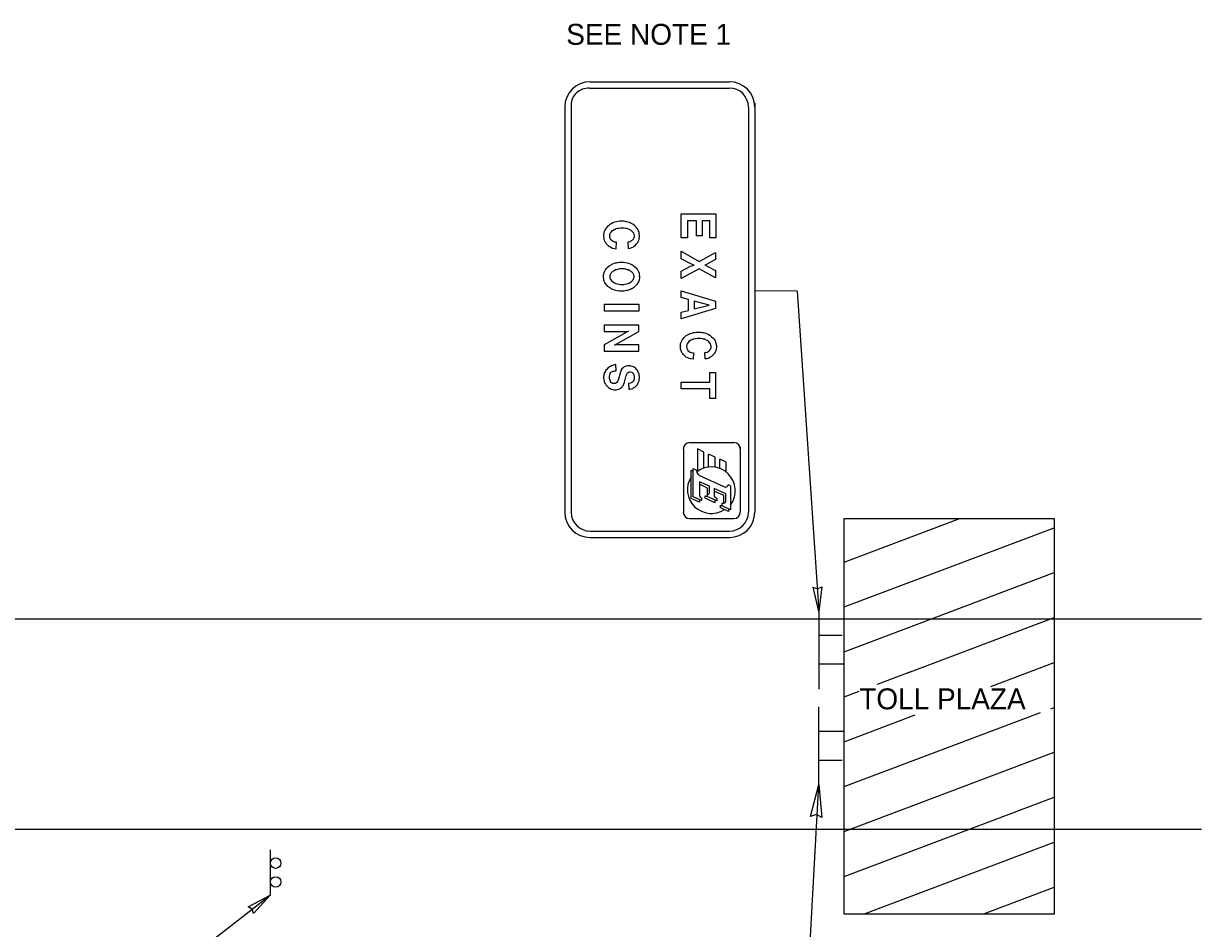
# Model space of a CAD drawing. Extents: x 46672 to 47298, y 5424 to 5829.
# Drawn here: x 46830.9 to 46988.5, y 5615.3 to 5736.4 of the extents above; entities that cross this region are included whole.
import ezdxf

# ---------------------------------------------------------------- set-up
doc = ezdxf.new("R2010")
doc.units = 0
for name, color, linetype in [('LeaderLine_dp', 7, 'Continuous'), ('RoadwayMisc', 7, 'Continuous'), ('SignSupport', 7, 'Continuous'), ('TextLabel', 7, 'Continuous'), ('TextShtNo', 7, 'Continuous')]:
    doc.layers.add(name, color=color, linetype=linetype)

msp = doc.modelspace()

# ---------------------------------------------------------------- linework, layer by layer
at = {"layer": 'LeaderLine_dp'}
for p, q in [((46934.39, 5700.63), (46928.71, 5700.64)), ((46934.39, 5700.63), (46937.26, 5657.75)), ((46934.39, 5582.49), (46937.26, 5634.61)), ((46845.12, 5605.25), (46863.86, 5619.8))]:
    msp.add_line(p, q, dxfattribs=at)
for points in [[(46937.26, 5657.75), (46936.52, 5660.99), (46937.1, 5660.78), (46937.67, 5661.05)], [(46937.26, 5634.61), (46937.68, 5630.2), (46936.95, 5630.57), (46936.15, 5630.32)], [(46863.86, 5619.8), (46861.62, 5617.34), (46861.46, 5617.93), (46860.92, 5618.25)]]:
    msp.add_lwpolyline(points, close=True, dxfattribs=at)
at = {"layer": 'RoadwayMisc'}
for p, q in [((46940.64, 5617.26), (46940.64, 5670.2)), ((46940.64, 5670.2), (46968.77, 5670.2)), ((46940.64, 5664.37), (46956.01, 5670.16)), ((46968.77, 5670.2), (46968.77, 5617.26)), ((46940.64, 5658.36), (46968.77, 5668.96)), ((46940.64, 5652.35), (46968.77, 5662.95)), ((46718.46, 5656.76), (46988.46, 5656.76)), ((46949.18, 5649.55), (46968.77, 5656.94)), ((46960.28, 5647.73), (46968.77, 5650.93)), ((46945.12, 5648.02), (46949.72, 5649.76)), ((46940.64, 5646.33), (46942.66, 5647.09)), ((46940.64, 5634.31), (46966.95, 5644.23)), ((46940.64, 5640.32), (46950.14, 5643.91)), ((46968.3, 5644.74), (46968.77, 5644.92)), ((46940.64, 5628.3), (46968.77, 5638.91)), ((46940.64, 5622.29), (46968.77, 5632.89)), ((46718.46, 5628.64), (46988.46, 5628.64)), ((46943.26, 5617.26), (46968.77, 5626.88)), ((46959.2, 5617.26), (46968.77, 5620.87)), ((46968.77, 5617.26), (46940.64, 5617.26))]:
    msp.add_line(p, q, dxfattribs=at)
at = {"layer": 'SignSupport'}
for p, q in [((46937.26, 5657.75), (46937.26, 5647.36)), ((46940.38, 5654.53), (46937.26, 5654.53)), ((46940.6, 5650.68), (46937.26, 5650.68)), ((46937.26, 5634.61), (46937.26, 5645)), ((46940.6, 5641.68), (46937.26, 5641.68)), ((46940.38, 5637.83), (46937.26, 5637.83)), ((46863.86, 5625.84), (46863.86, 5619.8))]:
    msp.add_line(p, q, dxfattribs=at)
for centre in [(46864.59, 5624.08), (46864.59, 5621.56)]:
    msp.add_circle(centre, 0.703, dxfattribs=at)
at = {"layer": 'TextShtNo'}
for p, q in [((46906.58, 5727.79), (46925.31, 5727.79)), ((46906.67, 5728.64), (46925.31, 5728.64)), ((46928.7, 5725.75), (46928.7, 5671.04)), ((46903.29, 5725.25), (46903.29, 5671.04)), ((46904.13, 5725.57), (46904.13, 5671.04)), ((46927.85, 5725.25), (46927.85, 5671.04)), ((46913.29, 5702.55), (46913.29, 5702.59)), ((46919.98, 5680.36), (46925.91, 5680.36)), ((46919.14, 5679.51), (46919.14, 5671.04)), ((46921.03, 5679.5), (46921.03, 5676.49)), ((46921.9, 5679.09), (46921.03, 5679.5)), ((46921.9, 5676.94), (46921.9, 5679.09)), ((46922.52, 5677.07), (46922.52, 5678.81)), ((46923.39, 5678.41), (46922.52, 5678.81)), ((46926.76, 5679.75), (46926.76, 5671.04)), ((46923.39, 5677.06), (46923.39, 5678.41)), ((46924.01, 5676.9), (46924.01, 5678.12)), ((46924.88, 5677.72), (46924.01, 5678.12)), ((46924.88, 5676.41), (46924.88, 5677.72)), ((46920.2, 5672.87), (46920.2, 5676.65)), ((46920.2, 5676.65), (46920.46, 5676.52)), ((46920.46, 5676.88), (46920.92, 5676.67)), ((46920.46, 5673.11), (46920.46, 5676.88)), ((46920.92, 5676.67), (46920.92, 5676.51)), ((46921.29, 5675.97), (46924.63, 5674.43)), ((46922.64, 5674.5), (46921.29, 5675.12)), ((46921.29, 5675.12), (46921.29, 5673.39)), ((46922.38, 5674.26), (46921.29, 5674.77)), ((46922.38, 5673.43), (46922.38, 5674.26)), ((46922.64, 5673.63), (46922.64, 5674.5)), ((46924.83, 5673.49), (46923.27, 5674.21)), ((46923.27, 5674.21), (46923.27, 5673.31)), ((46924.56, 5673.25), (46923.27, 5673.85)), ((46925.45, 5674.58), (46925.14, 5674.72)), ((46925.45, 5674.58), (46925.45, 5671.37)), ((46921.31, 5672.36), (46920.2, 5672.87)), ((46921.57, 5672.59), (46920.46, 5673.11)), ((46921.31, 5672.72), (46921.31, 5672.36)), ((46921.57, 5672.97), (46921.57, 5672.59)), ((46922.04, 5672.91), (46922.04, 5673.22)), ((46923.34, 5672.31), (46922.04, 5672.91)), ((46922.31, 5673.46), (46922.31, 5673.14)), ((46923.6, 5672.54), (46922.31, 5673.14)), ((46923.34, 5672.66), (46923.34, 5672.31)), ((46923.6, 5672.92), (46923.49, 5672.97)), ((46923.6, 5672.92), (46923.6, 5672.54)), ((46924.34, 5671.88), (46924.34, 5672.26)), ((46924.56, 5672.23), (46924.56, 5673.25)), ((46924.83, 5672.53), (46924.83, 5673.49)), ((46924.08, 5671.96), (46924.08, 5671.65)), ((46925.19, 5671.13), (46924.08, 5671.65)), ((46925.45, 5671.37), (46924.34, 5671.88)), ((46925.19, 5671.49), (46925.19, 5671.13)), ((46919.98, 5670.19), (46925.91, 5670.19)), ((46906.67, 5668.5), (46925.31, 5668.5)), ((46906.67, 5667.65), (46925.31, 5667.65))]:
    msp.add_line(p, q, dxfattribs=at)
for points in [[(46918.85, 5710.97), (46923.47, 5710.97), (46923.47, 5707.73), (46922.7, 5707.73), (46922.7, 5710.01), (46921.68, 5710.01), (46921.68, 5708.03), (46920.92, 5708.03), (46920.92, 5710.01), (46919.68, 5710.01), (46919.68, 5707.73), (46918.85, 5707.73), (46918.85, 5710.97)], [(46911.76, 5706.32), (46912.01, 5706.36), (46912.27, 5706.46), (46912.45, 5706.56), (46912.56, 5706.62), (46912.74, 5706.79), (46912.85, 5706.89), (46912.96, 5707.02), (46913.03, 5707.13), (46913.1, 5707.26), (46913.18, 5707.43), (46913.21, 5707.52), (46913.25, 5707.66), (46913.29, 5707.92), (46913.29, 5708.06), (46913.25, 5708.33), (46913.21, 5708.46), (46913.1, 5708.76), (46913.03, 5708.89), (46912.92, 5709.06), (46912.81, 5709.19), (46912.6, 5709.39), (46912.38, 5709.56), (46912.16, 5709.69), (46911.94, 5709.79), (46911.72, 5709.86), (46911.54, 5709.89), (46911.4, 5709.93), (46911.21, 5709.96), (46910.96, 5709.96), (46910.63, 5709.96), (46910.38, 5709.93), (46910.2, 5709.89), (46909.94, 5709.83), (46909.72, 5709.76), (46909.58, 5709.69), (46909.4, 5709.59), (46909.25, 5709.49), (46909.11, 5709.36), (46908.96, 5709.23), (46908.81, 5709.06), (46908.74, 5708.96), (46908.71, 5708.89), (46908.63, 5708.76), (46908.56, 5708.62), (46908.52, 5708.49), (46908.49, 5708.39), (46908.45, 5708.13), (46908.45, 5707.96), (46908.49, 5707.69), (46908.52, 5707.56), (46908.56, 5707.43), (46908.6, 5707.33), (46908.67, 5707.19), (46908.71, 5707.13), (46908.78, 5707.02), (46908.89, 5706.89), (46908.96, 5706.82), (46909.03, 5706.76), (46909.11, 5706.69), (46909.25, 5706.59), (46909.43, 5706.49), (46909.65, 5706.39), (46909.87, 5706.32), (46910.16, 5706.29)], [(46910.2, 5707.16), (46909.91, 5707.19), (46909.76, 5707.26), (46909.61, 5707.36), (46909.47, 5707.49), (46909.4, 5707.62), (46909.32, 5707.79), (46909.29, 5707.96), (46909.29, 5708.06), (46909.32, 5708.26), (46909.36, 5708.36), (46909.47, 5708.53), (46909.65, 5708.73), (46909.87, 5708.86), (46910.01, 5708.93), (46910.16, 5708.99), (46910.31, 5709.03), (46910.49, 5709.06), (46910.71, 5709.09), (46910.81, 5709.09), (46911, 5709.09), (46911.03, 5709.09), (46911.21, 5709.09), (46911.43, 5709.06), (46911.54, 5709.03), (46911.69, 5708.99), (46911.83, 5708.93), (46912.05, 5708.83), (46912.2, 5708.73), (46912.27, 5708.66), (46912.45, 5708.43), (46912.52, 5708.26), (46912.56, 5707.99), (46912.56, 5707.89), (46912.52, 5707.76), (46912.49, 5707.66), (46912.41, 5707.56), (46912.38, 5707.49), (46912.3, 5707.43), (46912.2, 5707.33), (46912.05, 5707.26), (46911.98, 5707.22), (46911.72, 5707.19)], [(46910.16, 5706.29), (46910.2, 5707.16)], [(46911.72, 5707.19), (46911.76, 5706.32)], [(46918.85, 5705.95), (46921.28, 5704.6), (46923.46, 5705.79), (46923.46, 5704.83), (46922.26, 5704.2), (46922.01, 5704.11), (46922.26, 5704.01), (46923.46, 5703.38), (46923.46, 5702.39), (46921.28, 5703.61), (46918.85, 5702.29), (46918.85, 5703.28), (46920.12, 5703.94), (46920.59, 5704.11), (46920.16, 5704.27), (46918.85, 5704.96), (46918.85, 5705.95)], [(46910.85, 5700.62), (46910.6, 5700.62), (46910.27, 5700.65), (46910.12, 5700.69), (46909.94, 5700.75), (46909.72, 5700.82), (46909.58, 5700.89), (46909.47, 5700.95), (46909.29, 5701.05), (46909.18, 5701.15), (46909.03, 5701.25), (46908.89, 5701.42), (46908.81, 5701.52), (46908.74, 5701.62), (46908.63, 5701.79), (46908.56, 5701.95), (46908.52, 5702.05), (46908.49, 5702.25), (46908.45, 5702.45), (46908.45, 5702.52), (46908.45, 5702.69), (46908.49, 5702.92), (46908.52, 5703.02), (46908.56, 5703.16), (46908.6, 5703.22), (46908.63, 5703.32), (46908.67, 5703.39), (46908.74, 5703.49), (46908.85, 5703.65), (46908.92, 5703.72), (46909.21, 5703.99), (46909.29, 5704.05), (46909.47, 5704.16), (46909.58, 5704.22), (46909.72, 5704.29), (46909.94, 5704.35), (46910.05, 5704.39), (46910.2, 5704.42), (46910.34, 5704.45), (46910.56, 5704.49), (46910.74, 5704.49), (46910.85, 5704.49)], [(46910.85, 5704.49), (46910.96, 5704.49), (46911.14, 5704.49), (46911.39, 5704.45), (46911.61, 5704.42), (46911.8, 5704.35), (46912.01, 5704.29), (46912.2, 5704.19), (46912.34, 5704.12), (46912.45, 5704.05), (46912.56, 5703.95), (46912.81, 5703.72), (46912.85, 5703.69), (46912.92, 5703.59), (46913, 5703.49), (46913.07, 5703.39), (46913.1, 5703.32), (46913.18, 5703.16), (46913.21, 5703.02), (46913.25, 5702.89), (46913.29, 5702.55)], [(46910.92, 5703.59), (46910.85, 5703.59), (46910.7, 5703.59), (46910.6, 5703.59), (46910.45, 5703.56), (46910.31, 5703.52), (46910.2, 5703.49), (46910.05, 5703.46), (46909.87, 5703.35), (46909.69, 5703.25), (46909.65, 5703.22), (46909.58, 5703.16), (46909.51, 5703.09), (46909.47, 5703.02), (46909.4, 5702.92), (46909.32, 5702.75), (46909.29, 5702.62), (46909.29, 5702.52)], [(46909.29, 5702.52), (46909.29, 5702.45), (46909.32, 5702.35), (46909.36, 5702.25), (46909.43, 5702.12), (46909.58, 5701.95), (46909.69, 5701.85), (46909.91, 5701.72), (46910.09, 5701.65), (46910.31, 5701.59), (46910.49, 5701.55), (46910.67, 5701.52), (46910.85, 5701.52), (46910.92, 5701.52)], [(46913.29, 5702.59), (46913.29, 5702.42), (46913.25, 5702.19), (46913.21, 5702.05), (46913.18, 5701.95), (46913.07, 5701.72), (46912.92, 5701.52), (46912.78, 5701.35), (46912.56, 5701.15), (46912.45, 5701.05), (46912.34, 5700.99), (46912.2, 5700.92), (46912.09, 5700.85), (46911.9, 5700.79), (46911.69, 5700.72), (46911.54, 5700.69), (46911.39, 5700.65), (46911.18, 5700.62), (46911.07, 5700.62), (46910.85, 5700.62)], [(46910.92, 5701.52), (46910.99, 5701.52), (46911.18, 5701.52), (46911.36, 5701.55), (46911.54, 5701.59), (46911.76, 5701.65), (46911.94, 5701.72), (46912.16, 5701.85), (46912.27, 5701.95), (46912.41, 5702.12), (46912.49, 5702.25), (46912.52, 5702.35), (46912.56, 5702.45), (46912.56, 5702.52), (46912.56, 5702.62), (46912.52, 5702.75), (46912.45, 5702.92), (46912.38, 5703.02), (46912.34, 5703.09), (46912.27, 5703.16), (46912.2, 5703.22), (46912.16, 5703.25), (46911.98, 5703.35), (46911.8, 5703.46), (46911.65, 5703.49), (46911.54, 5703.52), (46911.39, 5703.56), (46911.25, 5703.59), (46911.14, 5703.59), (46910.99, 5703.59), (46910.92, 5703.59)], [(46918.83, 5700.64), (46923.45, 5699.26), (46923.45, 5698.3), (46918.83, 5696.91), (46918.83, 5697.8), (46919.81, 5698.03), (46919.81, 5699.49), (46918.83, 5699.75), (46918.83, 5700.64)], [(46922.58, 5698.76), (46920.58, 5699.29), (46920.58, 5698.23), (46922.58, 5698.76)], [(46908.57, 5698.86), (46913.18, 5698.86), (46913.18, 5697.93), (46908.57, 5697.93), (46908.57, 5698.86)], [(46913.18, 5696.07), (46908.56, 5696.07), (46908.56, 5695.21), (46911.43, 5695.21), (46911.8, 5695.24), (46908.56, 5693.44), (46908.56, 5692.57), (46913.18, 5692.57), (46913.18, 5693.44), (46910.45, 5693.44), (46909.94, 5693.41), (46913.18, 5695.21), (46913.18, 5696.07)], [(46920.45, 5691.5), (46920.16, 5691.54), (46919.94, 5691.6), (46919.72, 5691.7), (46919.54, 5691.8), (46919.39, 5691.9), (46919.32, 5691.97), (46919.25, 5692.03), (46919.18, 5692.1), (46919.07, 5692.23), (46918.99, 5692.33), (46918.96, 5692.39), (46918.89, 5692.53), (46918.85, 5692.63), (46918.81, 5692.76), (46918.78, 5692.89), (46918.74, 5693.15), (46918.74, 5693.32), (46918.78, 5693.58), (46918.81, 5693.68), (46918.85, 5693.81), (46918.92, 5693.95), (46918.99, 5694.08), (46919.03, 5694.14), (46919.1, 5694.24), (46919.25, 5694.41), (46919.39, 5694.54), (46919.54, 5694.67), (46919.68, 5694.77), (46919.87, 5694.87), (46920.01, 5694.94), (46920.23, 5695), (46920.49, 5695.07), (46920.67, 5695.1), (46920.92, 5695.14), (46921.25, 5695.14), (46921.5, 5695.14), (46921.68, 5695.1), (46921.83, 5695.07), (46922.01, 5695.04), (46922.23, 5694.97), (46922.45, 5694.87), (46922.67, 5694.74), (46922.88, 5694.57), (46923.1, 5694.38), (46923.21, 5694.24), (46923.32, 5694.08), (46923.39, 5693.95), (46923.5, 5693.65), (46923.54, 5693.52), (46923.58, 5693.25), (46923.58, 5693.12), (46923.54, 5692.86), (46923.5, 5692.73), (46923.47, 5692.63), (46923.39, 5692.46), (46923.32, 5692.33), (46923.25, 5692.23), (46923.14, 5692.1), (46923.03, 5692), (46922.85, 5691.83), (46922.74, 5691.77), (46922.56, 5691.67), (46922.3, 5691.57), (46922.05, 5691.54)], [(46922.01, 5692.39), (46922.27, 5692.43), (46922.34, 5692.46), (46922.48, 5692.53), (46922.59, 5692.63), (46922.67, 5692.69), (46922.7, 5692.76), (46922.77, 5692.86), (46922.81, 5692.96), (46922.85, 5693.09), (46922.85, 5693.19), (46922.81, 5693.45), (46922.74, 5693.62), (46922.56, 5693.85), (46922.48, 5693.91), (46922.34, 5694.01), (46922.12, 5694.11), (46921.98, 5694.18), (46921.83, 5694.21), (46921.72, 5694.24), (46921.5, 5694.28), (46921.32, 5694.28), (46921.28, 5694.28), (46921.1, 5694.28), (46920.99, 5694.28), (46920.78, 5694.24), (46920.59, 5694.21), (46920.45, 5694.18), (46920.3, 5694.11), (46920.16, 5694.05), (46919.94, 5693.91), (46919.76, 5693.71), (46919.65, 5693.55), (46919.61, 5693.45), (46919.58, 5693.25), (46919.58, 5693.15), (46919.61, 5692.99), (46919.68, 5692.82), (46919.76, 5692.69), (46919.9, 5692.56), (46920.05, 5692.46), (46920.19, 5692.39), (46920.49, 5692.36)], [(46920.49, 5692.36), (46920.45, 5691.5)], [(46922.05, 5691.54), (46922.01, 5692.39)], [(46910.09, 5690.78), (46909.94, 5690.74), (46909.8, 5690.71), (46909.65, 5690.68), (46909.58, 5690.64), (46909.51, 5690.61), (46909.4, 5690.54), (46909.25, 5690.48), (46909.22, 5690.44), (46909.03, 5690.31), (46908.89, 5690.14), (46908.74, 5689.98), (46908.71, 5689.91), (46908.64, 5689.78), (46908.6, 5689.71), (46908.56, 5689.61), (46908.53, 5689.54), (46908.49, 5689.41), (46908.45, 5689.18), (46908.45, 5689.08), (46908.45, 5688.98), (46908.49, 5688.74), (46908.53, 5688.58), (46908.56, 5688.48), (46908.64, 5688.31), (46908.71, 5688.18), (46908.78, 5688.08), (46908.85, 5687.98), (46908.93, 5687.91), (46909.03, 5687.81), (46909.11, 5687.74), (46909.25, 5687.64), (46909.36, 5687.58), (46909.47, 5687.51)], [(46909.33, 5688.64), (46909.29, 5688.78), (46909.25, 5688.94), (46909.25, 5689.11), (46909.25, 5689.21), (46909.29, 5689.41), (46909.36, 5689.61), (46909.44, 5689.71), (46909.54, 5689.81), (46909.65, 5689.88), (46909.76, 5689.91), (46909.91, 5689.94), (46910.02, 5689.94)], [(46909.47, 5687.51), (46909.51, 5687.48), (46909.65, 5687.44), (46909.83, 5687.41), (46910.02, 5687.41), (46910.13, 5687.41), (46910.27, 5687.44), (46910.49, 5687.51), (46910.6, 5687.54), (46910.74, 5687.64), (46910.89, 5687.74), (46910.96, 5687.84), (46911.07, 5687.98), (46911.18, 5688.18), (46911.25, 5688.44), (46911.29, 5688.61), (46911.51, 5689.34), (46911.62, 5689.58), (46911.69, 5689.68), (46911.76, 5689.74), (46911.87, 5689.81), (46911.98, 5689.81)], [(46912.89, 5690.14), (46912.78, 5690.28), (46912.56, 5690.44), (46912.31, 5690.54), (46912.02, 5690.61), (46911.69, 5690.61), (46911.47, 5690.58), (46911.22, 5690.48), (46911.07, 5690.34), (46910.93, 5690.21), (46910.78, 5689.98), (46910.71, 5689.78), (46910.42, 5688.71), (46910.34, 5688.54), (46910.23, 5688.38), (46910.05, 5688.28), (46909.87, 5688.28), (46909.76, 5688.28)], [(46910.02, 5689.94), (46910.13, 5689.94), (46910.09, 5690.78)], [(46911.98, 5689.81), (46912.09, 5689.81), (46912.23, 5689.78), (46912.34, 5689.68), (46912.45, 5689.51), (46912.53, 5689.38), (46912.56, 5689.28), (46912.56, 5689.11), (46912.56, 5688.91), (46912.53, 5688.71), (46912.45, 5688.58), (46912.38, 5688.48), (46912.23, 5688.38), (46912.09, 5688.31), (46911.8, 5688.28)], [(46912.93, 5688.04), (46913, 5688.14), (46913.03, 5688.21), (46913.11, 5688.34), (46913.18, 5688.51), (46913.22, 5688.61), (46913.25, 5688.71), (46913.29, 5688.98), (46913.29, 5689.11), (46913.29, 5689.18), (46913.25, 5689.41), (46913.22, 5689.54), (46913.14, 5689.74), (46913.07, 5689.88), (46913.03, 5689.94), (46912.96, 5690.04), (46912.89, 5690.14)], [(46923.45, 5689.72), (46923.45, 5686.26), (46922.69, 5686.26), (46922.69, 5687.55), (46918.84, 5687.55), (46918.84, 5688.44), (46922.69, 5688.44), (46922.69, 5689.72), (46923.45, 5689.72)], [(46909.76, 5688.28), (46909.65, 5688.28), (46909.51, 5688.34), (46909.44, 5688.41), (46909.33, 5688.64)], [(46911.8, 5688.28), (46911.83, 5687.48), (46912.02, 5687.51), (46912.2, 5687.54), (46912.38, 5687.61), (46912.49, 5687.67), (46912.67, 5687.78), (46912.78, 5687.88), (46912.93, 5688.04)]]:
    msp.add_lwpolyline(points, dxfattribs=at)
for centre, radius, start, end in [((46906.67, 5725.25), 3.39, 90, 180), ((46925.31, 5725.25), 3.39, 360, 90), ((46925.31, 5725.25), 2.54, 360, 90), ((46919.98, 5679.51), 0.847, 90, 180), ((46925.91, 5679.51), 0.847, 360, 90), ((46922.9, 5673.91), 3.19, 322.9547, 128.1763), ((46922.88, 5674.06), 3.19, 148.1578, 303.3171), ((46906.67, 5671.04), 3.39, 180, 270), ((46906.67, 5671.04), 2.54, 180, 270), ((46919.98, 5671.04), 0.847, 180, 270), ((46925.31, 5671.04), 3.39, 270, 360), ((46925.31, 5671.04), 2.54, 270, 360), ((46925.91, 5671.04), 0.847, 270, 360)]:
    msp.add_arc(centre, radius, start, end, dxfattribs=at)
for centre, major_axis, start_param, end_param in [((46906.58, 5725.57), (2.45, 0), 1.570796, 3.141593), ((46921.59, 5676.51), (0.666, 0), 3.141593, 4.241135), ((46924.79, 5674.71), (0.35, 0), 4.241328, 6.314398), ((46921.81, 5673.39), (0.52, 0), 3.141593, 4.232591), ((46922.2, 5673.48), (0.333, 0), 4.227342, 5.041732), ((46922.42, 5673.63), (0.219, 0), 4.144801, 6.283185), ((46923.68, 5673.31), (0.416, 0), 3.141593, 4.241405), ((46924.49, 5672.53), (0.333, 0), 4.227342, 6.283185), ((46924.23, 5672.22), (0.333, 0), 4.227342, 5.041732)]:
    msp.add_ellipse(centre, major_axis=major_axis, ratio=0.906668, start_param=start_param, end_param=end_param, dxfattribs=at)

# ---------------------------------------------------------------- texts
at = {"layer": 'TextLabel'}
for s, p in [('SEE NOTE 1', (46903.47, 5733.58)), ('TOLL PLAZA', (46942.68, 5644.66))]:
    msp.add_text(s, height=2.8, dxfattribs=at).set_placement(p)

doc.saveas('drawing.dxf')
